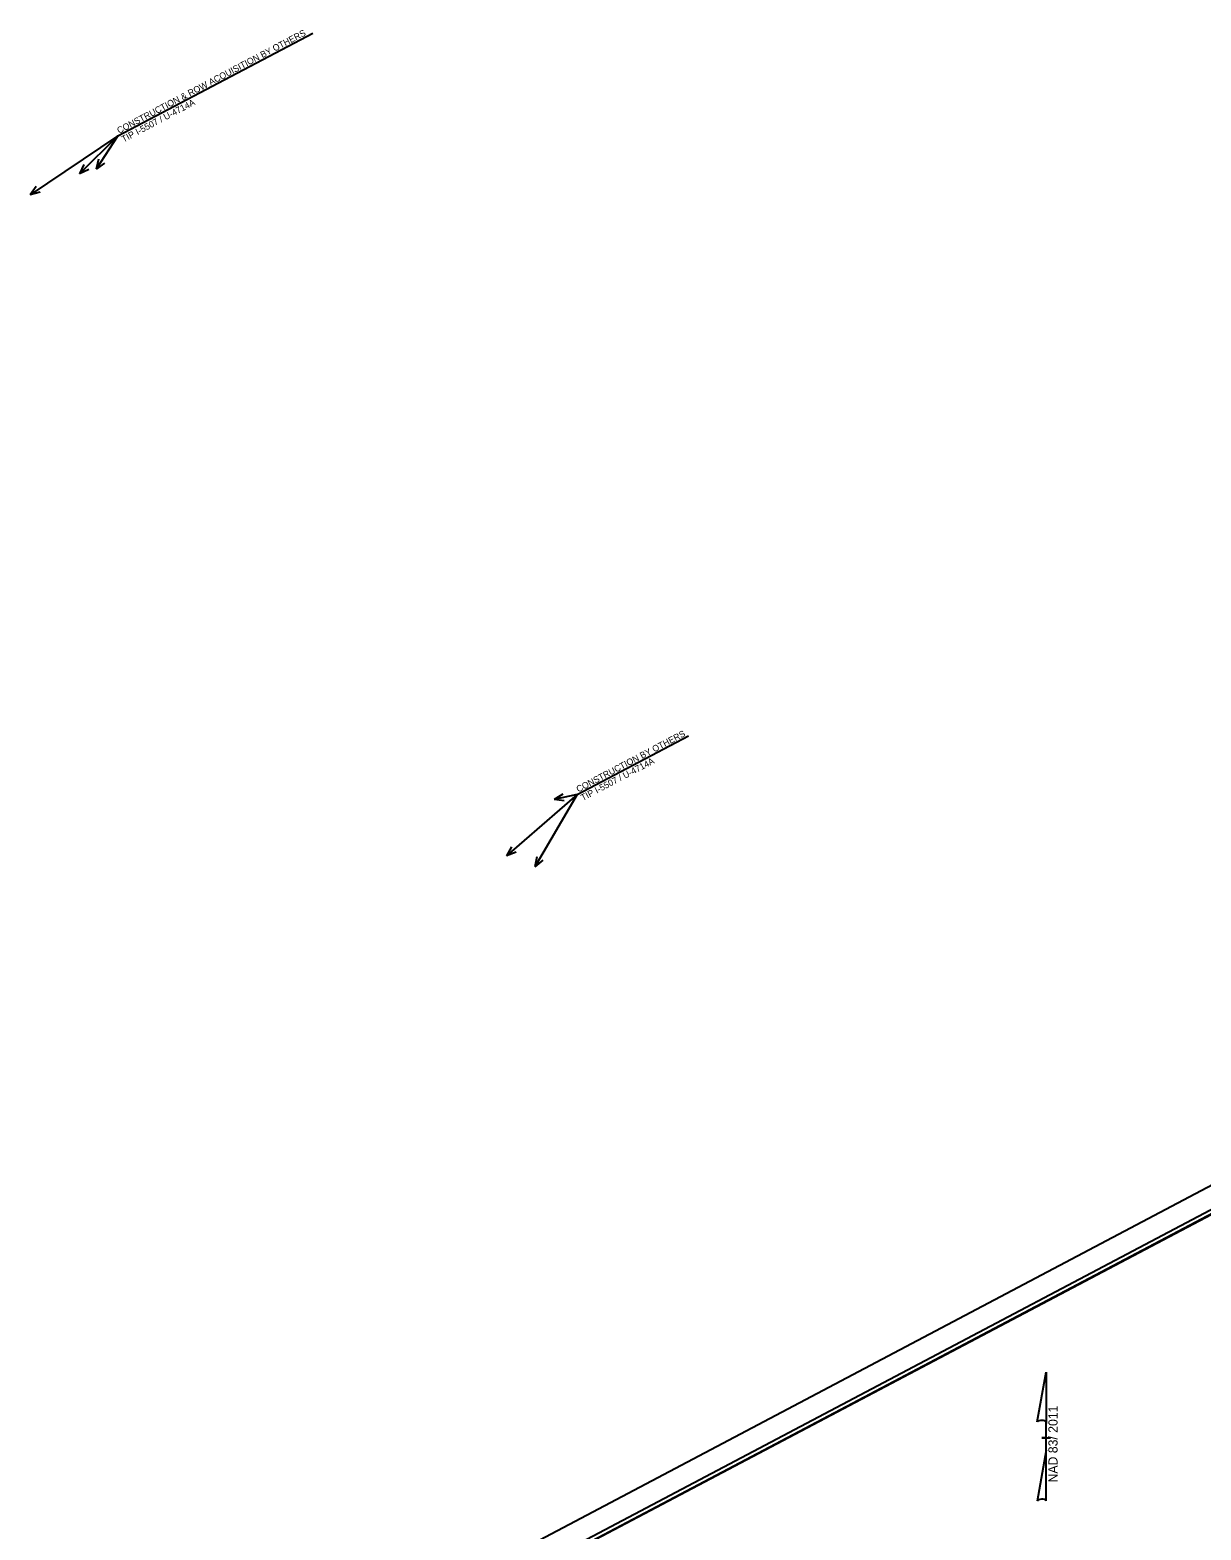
# Model space of a CAD drawing. Extents: x 1487165 to 1493546, y 497841 to 501709.
# Drawn here: x 1487165 to 1488254, y 499122 to 500516 of the extents above; entities that cross this region are included whole.
import ezdxf

# ---------------------------------------------------------------- set-up
doc = ezdxf.new("R2010")
doc.units = 0
for name, color, linetype in [('Prop Horizontal Alignment Station Label', 7, 'Continuous'), ('Prop North Arrow NAD83 for Plan Sheets CELL', 7, 'Continuous'), ('Scratch_Level_3', 7, 'Continuous'), ('Sheet Block Title CELL', 7, 'Continuous'), ('Sheet Clip Boundary CELL', 7, 'Continuous'), ('Sheet Plot Border Inside CELL', 7, 'Continuous'), ('Sheet Plot Border Outside CELL', 7, 'Continuous')]:
    doc.layers.add(name, color=color, linetype=linetype)

msp = doc.modelspace()

# ---------------------------------------------------------------- linework, layer by layer
at = {"layer": 'Prop Horizontal Alignment Station Label'}
for p, q in [((1487247, 500417.9), (1487428.2, 500513.5)), ((1487247, 500417.9), (1487165.4, 500363.3)), ((1487247, 500417.9), (1487211.4, 500382.8)), ((1487247, 500417.9), (1487227, 500386.9)), ((1487229.2, 500396.2), (1487227, 500386.9)), ((1487215.5, 500391.4), (1487211.4, 500382.8)), ((1487220.1, 500386.8), (1487211.4, 500382.8)), ((1487234.7, 500392.7), (1487227, 500386.9)), ((1487171.1, 500371), (1487165.4, 500363.3)), ((1487174.7, 500365.6), (1487165.4, 500363.3)), ((1487673.9, 499805.8), (1487777.4, 499860.5)), ((1487673.9, 499805.8), (1487608.2, 499748.9)), ((1487673.9, 499805.8), (1487634.6, 499738.7)), ((1487660.6, 499806.3), (1487652.5, 499801.2)), ((1487673.9, 499805.8), (1487652.5, 499801.2)), ((1487661.9, 499799.9), (1487652.5, 499801.2)), ((1487612.9, 499757.3), (1487608.2, 499748.9)), ((1487617.2, 499752.3), (1487608.2, 499748.9)), ((1487636.4, 499748.1), (1487634.6, 499738.7)), ((1487642, 499744.8), (1487634.6, 499738.7))]:
    msp.add_line(p, q, dxfattribs=at)
at = {"layer": 'Prop North Arrow NAD83 for Plan Sheets CELL'}
for p, q in [((1488101.7, 499222.8), (1488109.9, 499269.1)), ((1488110, 499269.1), (1488109.9, 499269.1)), ((1488110, 499269.1), (1488109.9, 499269.1)), ((1488110, 499269.1), (1488110, 499221.3)), ((1488110, 499196.5), (1488110, 499222.7)), ((1488110, 499221.3), (1488110, 499222.7)), ((1488110, 499196.5), (1488101.6, 499149.3)), ((1488106, 499208.1), (1488105.9, 499208.1)), ((1488106, 499208.1), (1488114, 499208.1)), ((1488109.5, 499208.1), (1488106, 499208.1)), ((1488110, 499149.5), (1488110, 499196.5))]:
    msp.add_line(p, q, dxfattribs=at)
for centre, start_param, end_param in [((1488105.9, 499222.3), 0.216388, 2.908219), ((1488105.9, 499149.1), 0.201328, 3.141593)]:
    msp.add_ellipse(centre, major_axis=(4.23, -0.03), ratio=0.461098, start_param=start_param, end_param=end_param, dxfattribs=at)
at = {"layer": 'Scratch_Level_3'}
msp.add_lwpolyline([(1487512.6, 499019.7), (1488662.1, 499625.8), (1488771.2, 499418.9), (1488936.6, 499506), (1489317.2, 498785.2), (1488242.7, 498217.8), (1488120.4, 498369.2), (1487949.5, 498194.2)], close=True, dxfattribs=at)
at = {"layer": 'Sheet Block Title CELL'}
msp.add_lwpolyline([(1488826.9, 499713.7), (1487500.5, 499013.3), (1487990.8, 498084.8), (1489317.2, 498785.2)], close=True, dxfattribs=at)
at = {"layer": 'Sheet Clip Boundary CELL'}
msp.add_lwpolyline([(1487500.5, 499013.2), (1488662.1, 499625.8), (1488771.2, 499418.9), (1488936.6, 499506), (1489317.2, 498785.1), (1487990.8, 498084.7)], close=True, dxfattribs=at)
at = {"layer": 'Sheet Plot Border Inside CELL'}
msp.add_lwpolyline([(1488835.9, 499722.2), (1487363.2, 498944.6), (1487856.2, 498010.8), (1489329, 498788.5)], close=True, dxfattribs=at)
at = {"layer": 'Sheet Plot Border Outside CELL'}
msp.add_lwpolyline([(1488830.6, 499742), (1487342.4, 498956.2), (1487854.1, 497987.1), (1489342.3, 498772.9)], close=True, dxfattribs=at)

# ---------------------------------------------------------------- texts
at = {"layer": 'Prop Horizontal Alignment Station Label'}
for s, p in [('CONSTRUCTION & ROW ACQUISITION BY OTHERS', (1487248.2, 500419.8)), ('TIP I-5507 / U-4714A', (1487252.4, 500411.8)), ('CONSTRUCTION BY OTHERS', (1487675.1, 499807.7)), ('TIP I-5507 / U-4714A', (1487679.3, 499799.8))]:
    msp.add_text(s, height=6, rotation=27.8351, dxfattribs=at).set_placement(p)
at = {"layer": 'Prop North Arrow NAD83 for Plan Sheets CELL'}
msp.add_text('NAD 83/ 2011', height=8.5, rotation=90, dxfattribs=at).set_placement((1488120.5, 499166.6))

doc.saveas('drawing.dxf')
